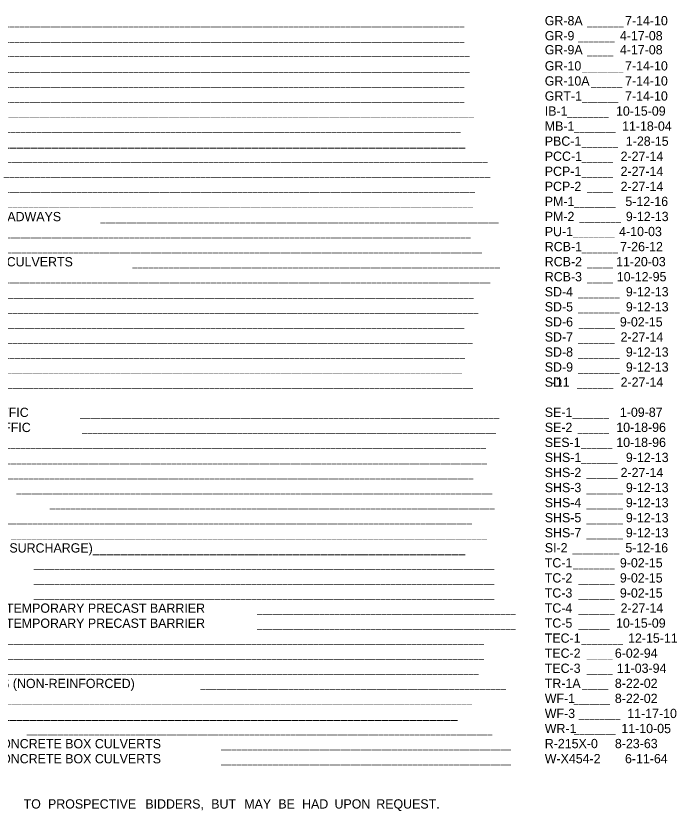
# Model space of a CAD drawing. Extents: x 1224738 to 1230974, y 151304 to 152345.
# Drawn here: x 1227596.7 to 1227963.5, y 151437.2 to 151878.6 of the extents above; entities that cross this region are included whole.
import ezdxf

# ---------------------------------------------------------------- set-up
doc = ezdxf.new("R2010")
doc.units = 0
doc.layers.add('R_Dimension', color=7, linetype='Continuous')

msp = doc.modelspace()

# ---------------------------------------------------------------- texts
at = {"layer": 'R_Dimension'}
for s, height, p in [('GR-8A', 5.144, (1227890.12, 151873.36)), ('7-14-10', 5.144, (1227934.67, 151873.36)), ('_________________________________________________________________________________________________________________________________________', 3.85819, (1227452.35, 151873.28)), ('GR-9', 5.144, (1227890.12, 151865)), ('_______', 3.858, (1227913.7, 151873.36)), ('4-17-08', 5.144, (1227931.79, 151865)), ('_________________________________________________________________________________________________________________________________________', 3.85819, (1227452.35, 151864.92)), ('_______', 3.858, (1227908.68, 151865)), ('GR-9A', 5.144, (1227890.12, 151857.22)), ('4-17-08', 5.144, (1227931.79, 151857.21)), ('__________________________________________________________________________________________________________________________________________', 3.85819, (1227452.35, 151857.14)), ('_____', 3.858, (1227913.7, 151857.22)), ('GR-10', 5.144, (1227890.12, 151848.28)), ('7-14-10', 5.144, (1227934.67, 151848.28)), ('__________________________________________________________________________________________________________________________________________', 3.85819, (1227452.35, 151848.2)), ('________', 3.858, (1227910.78, 151848.28)), ('GR-10A', 5.144, (1227890.12, 151839.92)), ('7-14-10', 5.144, (1227934.67, 151839.92)), ('_________________________________________________________________________________________________________________________________________', 3.85819, (1227452.35, 151839.84)), ('______', 3.858, (1227915.81, 151839.92)), ('GRT-1', 5.144, (1227890.12, 151831.56)), ('7-14-10', 5.144, (1227934.67, 151831.56)), ('_________________________________________________________________________________________________________________________________________', 3.85819, (1227452.35, 151831.48)), ('_______', 3.858, (1227910.78, 151831.56)), ('IB-1', 5.144, (1227890.12, 151823.2)), ('10-15-09', 5.144, (1227929.64, 151823.2)), ('____________________________________________________________________________________________________________________________', 3.85819, (1227495.05, 151823.12)), ('MB-1', 5.144, (1227890.12, 151814.84)), ('________', 3.858, (1227902.6, 151823.2)), ('11-18-04', 5.144, (1227933, 151814.84)), ('_____________________________________________________________________________________________________________________________________________', 3.85819, (1227438.74, 151814.76)), (' CULVERTS_________________________________________________________________________________________', 5.1443, (1227466.81, 151806.4)), ('PBC-1', 5.144, (1227890.12, 151806.48)), ('________', 3.858, (1227906.41, 151814.84)), ('1-28-15', 5.144, (1227935.11, 151806.48)), ('PCC-1', 5.144, (1227890.12, 151798.12)), ('_______', 3.858, (1227910.62, 151806.48)), ('2-27-14', 5.144, (1227932.19, 151798.12)), ('____________________________________________________________________________________________________', 3.8582, (1227571.52, 151798.04)), ('PCP-1', 5.144, (1227890.12, 151789.76)), ('______', 3.858, (1227910.62, 151798.12)), ('2-27-14', 5.144, (1227932.19, 151789.76)), ('______', 3.858, (1227910.62, 151789.76)), ('______________________________________________________________________________________________', 3.8582, (1227590.07, 151789.68)), ('PCP-2', 5.144, (1227890.12, 151781.4)), ('2-27-14', 5.144, (1227932.19, 151781.4)), ('_______________________________________________________________________________________________________________________', 3.85819, (1227509.95, 151781.32)), ('_____', 3.858, (1227913.54, 151781.4)), ('PM-1', 5.144, (1227890.12, 151773.04)), ('5-12-16', 5.144, (1227934.83, 151773.04)), ('________________________________________________________________________________________________________________________________', 3.85819, (1227482.98, 151772.97)), ('________', 3.858, (1227906.41, 151773.04)), ('PERMANENT PAVEMENT MARKING ON ACCESS CONTROLLED ROADWAYS', 5.1443, (1227371.42, 151764.61)), ('PM-2', 5.144, (1227890.12, 151764.68)), ('9-12-13', 5.144, (1227935.11, 151764.68)), ('_____________________________________________________________________________', 3.8582, (1227643.54, 151764.61)), ('________', 3.858, (1227909.32, 151764.68)), ('PU-1', 5.144, (1227890.12, 151756.32)), ('4-10-03', 5.144, (1227931.38, 151756.32)), ('______________________________________________________________________________________________________________________________', 3.85819, (1227487.35, 151756.25)), ('________', 3.858, (1227905.84, 151756.32)), ('RCB-1', 5.144, (1227890.12, 151747.96)), ('7-26-12', 5.144, (1227931.95, 151747.96)), ('_________________________________________________________________________________________________________', 3.85819, (1227553.94, 151747.89)), ('RCB-2', 5.144, (1227890.12, 151739.61)), ('_______', 3.858, (1227910.62, 151747.96)), ('11-20-03', 5.144, (1227929.68, 151739.6)), ('EXCAVATION PAY LIMITS, BACKFILL, & SOLID SODDING FOR BOX CULVERTS', 5.1443, (1227371.42, 151739.53)), ('_______________________________________________________________________', 3.8582, (1227661.45, 151739.53)), ('RCB-3', 5.144, (1227890.12, 151731.25)), ('_____', 3.858, (1227913.54, 151739.61)), ('10-12-95', 5.144, (1227930.09, 151731.25)), ('__________________________________________________________________________________________________', 3.8582, (1227578.65, 151731.17)), ('SD-4', 5.144, (1227890.12, 151722.89)), ('_____', 3.858, (1227913.54, 151731.25)), ('9-12-13', 5.144, (1227935.11, 151722.89)), ('_____________________________________________________________________________________________________________________________', 3.85819, (1227491.89, 151722.81)), ('SD-5', 5.144, (1227890.12, 151714.53)), ('________', 3.858, (1227908.68, 151722.89)), ('9-12-13', 5.144, (1227935.11, 151714.53)), ('___________________________________________________________________________________________________________________', 3.85819, (1227523.24, 151714.45)), ('SD-6', 5.144, (1227890.12, 151706.17)), ('________', 3.858, (1227908.68, 151714.53)), ('9-02-15', 5.144, (1227931.79, 151706.17)), ('_____________________________________________________________________________________________________________________________________', 3.85819, (1227463.78, 151706.09)), ('_______', 3.858, (1227908.92, 151706.17)), ('SD-7', 5.144, (1227890.12, 151697.81)), ('2-27-14', 5.144, (1227932.19, 151697.81)), ('________________________________________________________________________________________________________________________', 3.85819, (1227505.82, 151697.73)), ('_______', 3.858, (1227908.68, 151697.81)), ('SD-8', 5.144, (1227890.12, 151689.45)), ('9-12-13', 5.144, (1227935.11, 151689.45)), ('___________________________________________________________________________________________________________________________________', 3.85819, (1227469.93, 151689.37)), ('________', 3.858, (1227908.68, 151689.45)), ('SD-9', 5.144, (1227890.12, 151681.09)), ('9-12-13', 5.144, (1227935.11, 151681.09)), ('_________________________________________________________________________________________________________________________________________________', 3.85819, (1227428.05, 151681.01)), ('________', 3.858, (1227908.68, 151681.09)), ('SD', 5.144, (1227890.12, 151672.74)), ('  -11', 5.144, (1227890.12, 151672.73)), ('2-27-14', 5.144, (1227932.19, 151672.73)), ('_______________________________________________________________________________________________________________________________', 3.85819, (1227485.81, 151672.65)), ('_______', 3.858, (1227908.03, 151672.73)), ('TABLES AND METHOD OF SUPERELEVATION FOR ONE-WAY TRAFFIC', 5.1443, (1227371.42, 151655.93)), ('SE-1', 5.144, (1227890.12, 151656.01)), ('1-09-87', 5.144, (1227931.79, 151656.01)), ('TABLES AND METHOD OF SUPERELEVATION FOR TWO-WAY TRAFFIC', 5.1443, (1227371.42, 151647.57)), ('_________________________________________________________________________________', 3.8582, (1227632.36, 151655.93)), ('SE-2', 5.144, (1227890.12, 151647.65)), ('_______', 3.858, (1227905.52, 151656.01)), ('10-18-96', 5.144, (1227929.8, 151647.65)), ('________________________________________________________________________________', 3.8582, (1227633.42, 151647.57)), ('SES-1', 5.144, (1227890.12, 151639.29)), ('______', 3.858, (1227908.43, 151647.65)), ('10-18-96', 5.144, (1227929.8, 151639.29)), ('_______________________________________________________________________________________________', 3.8582, (1227584.89, 151639.21)), ('SHS-1', 5.144, (1227890.12, 151630.93)), ('______', 3.858, (1227910.38, 151639.29)), ('9-12-13', 5.144, (1227935.11, 151630.93)), ('________________________________________________________________________________________________', 3.8582, (1227582.46, 151630.86)), ('_______', 3.858, (1227910.38, 151630.93)), ('SHS-2', 5.144, (1227890.12, 151622.57)), ('2-27-14', 5.144, (1227932.19, 151622.57)), ('______________________________________________________________________________________________________________________________', 3.85819, (1227488.97, 151622.5)), ('______', 3.858, (1227913.29, 151622.57)), ('SHS-3', 5.144, (1227890.12, 151614.21)), ('9-12-13', 5.144, (1227935.11, 151614.21)), ('____________________________________________________________________________________________', 3.8582, (1227596.96, 151614.14)), ('_______', 3.858, (1227913.29, 151614.21)), ('SHS-4', 5.144, (1227890.12, 151605.85)), ('9-12-13', 5.144, (1227935.11, 151605.85)), ('______________________________________________________________________________________', 3.8582, (1227615.59, 151605.78)), ('_______', 3.858, (1227913.29, 151605.85)), ('SHS-5', 5.144, (1227890.12, 151597.5)), ('9-12-13', 5.144, (1227935.11, 151597.49)), ('___________________________________________________________________________________________________________________________', 3.85819, (1227496.83, 151597.42)), ('_______', 3.858, (1227913.29, 151597.5)), ('SHS-7', 5.144, (1227890.12, 151589.14)), ('9-12-13', 5.144, (1227935.11, 151589.14)), ('REINFORCED CONCRETE RETAINING WALL (WITHOUT LIVE LOAD SURCHARGE)______________________________________________________', 5.14425, (1227371.42, 151580.7)), ('____________________________________________________________________________________________', 3.8582, (1227594.04, 151589.06)), ('SI-2', 5.144, (1227890.12, 151580.78)), ('_______', 3.858, (1227913.29, 151589.14)), ('5-12-16', 5.144, (1227934.83, 151580.78)), ('TC-1', 5.144, (1227890.12, 151572.42)), ('_________', 3.858, (1227905.52, 151580.78)), ('9-02-15', 5.144, (1227931.79, 151572.42)), ('_________________________________________________________________________________________', 3.8582, (1227606.68, 151572.34)), ('TC-2', 5.144, (1227890.12, 151564.06)), ('________', 3.858, (1227905.92, 151572.42)), ('9-02-15', 5.144, (1227931.79, 151564.06)), ('_________________________________________________________________________________________', 3.8582, (1227606.68, 151563.98)), ('TC-3', 5.144, (1227890.12, 151555.7)), ('_______', 3.858, (1227908.84, 151564.06)), ('9-02-15', 5.144, (1227931.79, 151555.7)), ('STANDARD TRAFFIC CONTROLS FOR HIGHWAY CONSTRUCTION-TEMPORARY PRECAST BARRIER', 5.1443, (1227371.42, 151547.26)), ('_________________________________________________________________________________________', 3.8582, (1227606.68, 151555.62)), ('TC-4', 5.144, (1227890.12, 151547.34)), ('_______', 3.858, (1227908.84, 151555.7)), ('2-27-14', 5.144, (1227932.19, 151547.34)), ('__________________________________________________', 3.8582, (1227730.47, 151547.26)), ('_______', 3.858, (1227908.84, 151547.34)), ('STANDARD TRAFFIC CONTROLS FOR HIGHWAY CONSTRUCTION-TEMPORARY PRECAST BARRIER', 5.1443, (1227371.42, 151538.9)), ('TC-5', 5.144, (1227890.12, 151538.98)), ('10-15-09', 5.144, (1227929.64, 151538.98)), ('__________________________________________________', 3.8582, (1227730.47, 151538.9)), ('______', 3.858, (1227908.84, 151538.98)), ('TEC-1', 5.144, (1227890.12, 151530.62)), ('12-15-11', 5.144, (1227936.33, 151530.62)), ('___________________________________________________________________________________________________________________', 3.85819, (1227526.32, 151530.54)), ('________', 3.858, (1227910.54, 151530.62)), ('TEC-2', 5.144, (1227890.12, 151522.26)), ('6-02-94', 5.144, (1227929, 151522.26)), ('___________________________________________________________________________________________________________________', 3.85819, (1227526.32, 151522.18)), ('_____', 3.858, (1227913.46, 151522.26)), ('TEC-3', 5.144, (1227890.12, 151513.9)), ('11-03-94', 5.144, (1227930.09, 151513.9)), ('DETAILS OF STANDARD TURNOUT FOR ENTRANCE & EXIT RAMPS (NON-REINFORCED)', 5.1443, (1227371.42, 151505.46)), ('__________________________________________________________________________________________________________________', 3.85819, (1227526.32, 151513.82)), ('_____', 3.858, (1227913.46, 151513.9)), ('TR-1A', 5.144, (1227890.12, 151505.54)), ('8-22-02', 5.144, (1227929, 151505.54)), ('___________________________________________________________', 3.8582, (1227699.2, 151505.46)), ('WF-1', 5.144, (1227890.12, 151497.18)), ('_____', 3.858, (1227910.94, 151505.54)), ('8-22-02', 5.144, (1227929, 151497.18)), (' FENCE__________________________________________________________________________________________________________', 5.14425, (1227410.9, 151488.75)), ('_________________________________________________________________________________________________________________________________', 3.85819, (1227479.49, 151497.1)), ('WF-3', 5.144, (1227890.12, 151488.82)), ('_______', 3.858, (1227906.16, 151497.18)), ('11-17-10', 5.144, (1227935.88, 151488.82)), ('WR-1', 5.144, (1227890.12, 151480.46)), ('________', 3.858, (1227909.08, 151488.82)), ('11-10-05', 5.144, (1227932.6, 151480.46)), ('DETAILS OF STANDARD BARREL SECTIONS FOR REINFORCED CONCRETE BOX CULVERTS', 5.1443, (1227371.42, 151472.03)), ('__________________________________________________________________________________________', 3.8582, (1227602.79, 151480.39)), ('R-215X-0', 5.144, (1227890.12, 151472.1)), ('________', 3.858, (1227906.41, 151480.46)), ('8-23-63', 5.144, (1227929.03, 151472.1)), ('________________________________________________________', 3.8582, (1227710.62, 151472.03)), ('DETAILS OF STANDARD BARREL SECTIONS FOR REINFORCED CONCRETE BOX CULVERTS', 5.1443, (1227371.42, 151463.67)), ('W-X454-2', 5.144, (1227890.12, 151463.74)), ('6-11-64', 5.144, (1227934.62, 151463.74)), ('________________________________________________________', 3.8582, (1227710.62, 151463.67)), (' TO', 5.144, (1227599.08, 151438.59)), (' PROSPECTIVE', 5.1443, (1227612.61, 151438.59)), (' BIDDERS,', 5.144, (1227666.61, 151438.59)), (' BUT', 5.144, (1227703.18, 151438.59)), (' MAY', 5.144, (1227721.49, 151438.59)), (' BE', 5.144, (1227740.41, 151438.59)), (' HAD', 5.144, (1227753.57, 151438.59)), (' UPON', 5.144, (1227771.56, 151438.59)), (' REQUEST.', 5.144, (1227794.73, 151438.59))]:
    msp.add_text(s, height=height, dxfattribs=at).set_placement(p)

doc.saveas('drawing.dxf')
